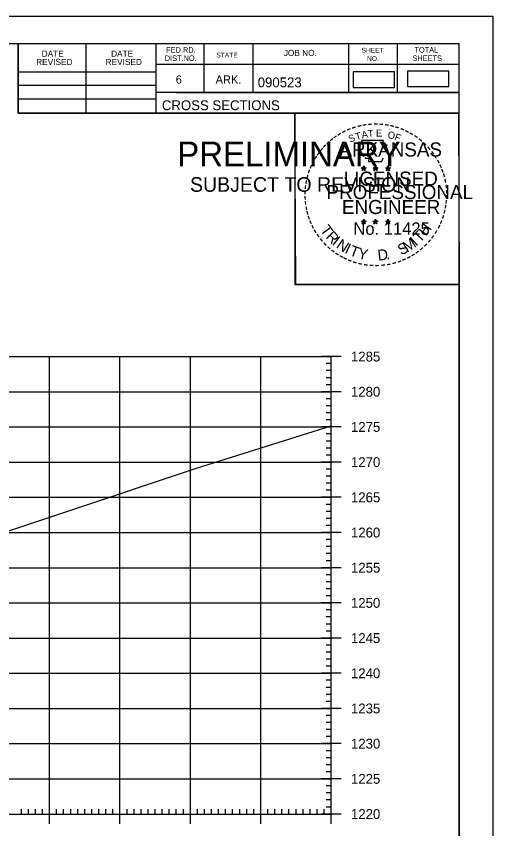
# Model space of a CAD drawing. Extents: x 1406028 to 1412453, y 321733 to 325986.
# Drawn here: x 1410874.9 to 1410942.5, y 322148 to 322263.4 of the extents above; entities that cross this region are included whole.
import ezdxf

# ---------------------------------------------------------------- set-up
doc = ezdxf.new("R2010")
doc.units = 0
for name, color, linetype in [('R_Axis', 7, 'Continuous'), ('R_Axis Annot', 7, 'Continuous'), ('R_Border', 7, 'Continuous'), ('R_Border PE', 7, 'Continuous'), ('R_Border Prem', 7, 'Continuous'), ('R_Exist Surface', 7, 'Continuous'), ('R_Fin Surface', 7, 'Continuous'), ('R_Grid', 7, 'Continuous'), ('R_No Plot', 7, 'Continuous')]:
    doc.layers.add(name, color=color, linetype=linetype)

msp = doc.modelspace()

# ---------------------------------------------------------------- linework, layer by layer
at = {"layer": 'R_Axis'}
for p, q in [((1410920.99, 322215.09), (1410918.19, 322215.09)), ((1410919.59, 322214.09), (1410918.89, 322214.09)), ((1410919.59, 322150.09), (1410919.59, 322215.09)), ((1410919.59, 322213.09), (1410918.89, 322213.09)), ((1410919.59, 322212.09), (1410918.89, 322212.09)), ((1410919.59, 322211.09), (1410918.89, 322211.09)), ((1410920.99, 322210.09), (1410918.19, 322210.09)), ((1410919.59, 322209.09), (1410918.89, 322209.09)), ((1410919.59, 322208.09), (1410918.89, 322208.09)), ((1410919.59, 322207.09), (1410918.89, 322207.09)), ((1410919.59, 322206.09), (1410918.89, 322206.09)), ((1410920.99, 322205.09), (1410918.19, 322205.09)), ((1410919.59, 322204.09), (1410918.89, 322204.09)), ((1410919.59, 322203.09), (1410918.89, 322203.09)), ((1410919.59, 322202.09), (1410918.89, 322202.09)), ((1410919.59, 322201.09), (1410918.89, 322201.09)), ((1410920.99, 322200.09), (1410918.19, 322200.09)), ((1410919.59, 322199.09), (1410918.89, 322199.09)), ((1410919.59, 322198.09), (1410918.89, 322198.09)), ((1410919.59, 322197.09), (1410918.89, 322197.09)), ((1410919.59, 322196.09), (1410918.89, 322196.09)), ((1410920.99, 322195.09), (1410918.19, 322195.09)), ((1410919.59, 322194.09), (1410918.89, 322194.09)), ((1410919.59, 322193.09), (1410918.89, 322193.09)), ((1410919.59, 322192.09), (1410918.89, 322192.09)), ((1410919.59, 322191.09), (1410918.89, 322191.09)), ((1410920.99, 322190.09), (1410918.19, 322190.09)), ((1410919.59, 322189.09), (1410918.89, 322189.09)), ((1410919.59, 322188.09), (1410918.89, 322188.09)), ((1410919.59, 322187.09), (1410918.89, 322187.09)), ((1410919.59, 322186.09), (1410918.89, 322186.09)), ((1410920.99, 322185.09), (1410918.19, 322185.09)), ((1410919.59, 322184.09), (1410918.89, 322184.09)), ((1410919.59, 322183.09), (1410918.89, 322183.09)), ((1410919.59, 322182.09), (1410918.89, 322182.09)), ((1410919.59, 322181.09), (1410918.89, 322181.09)), ((1410920.99, 322180.09), (1410918.19, 322180.09)), ((1410919.59, 322179.09), (1410918.89, 322179.09)), ((1410919.59, 322178.09), (1410918.89, 322178.09)), ((1410919.59, 322177.09), (1410918.89, 322177.09)), ((1410919.59, 322176.09), (1410918.89, 322176.09)), ((1410920.99, 322175.09), (1410918.19, 322175.09)), ((1410919.59, 322174.09), (1410918.89, 322174.09)), ((1410919.59, 322173.09), (1410918.89, 322173.09)), ((1410919.59, 322172.09), (1410918.89, 322172.09)), ((1410919.59, 322171.09), (1410918.89, 322171.09)), ((1410920.99, 322170.09), (1410918.19, 322170.09)), ((1410919.59, 322169.09), (1410918.89, 322169.09)), ((1410919.59, 322168.09), (1410918.89, 322168.09)), ((1410919.59, 322167.09), (1410918.89, 322167.09)), ((1410919.59, 322166.09), (1410918.89, 322166.09)), ((1410920.99, 322165.09), (1410918.19, 322165.09)), ((1410919.59, 322164.09), (1410918.89, 322164.09)), ((1410919.59, 322163.09), (1410918.89, 322163.09)), ((1410919.59, 322162.09), (1410918.89, 322162.09)), ((1410919.59, 322161.09), (1410918.89, 322161.09)), ((1410920.99, 322160.09), (1410918.19, 322160.09)), ((1410919.59, 322159.09), (1410918.89, 322159.09)), ((1410919.59, 322158.09), (1410918.89, 322158.09)), ((1410919.59, 322157.09), (1410918.89, 322157.09)), ((1410919.59, 322156.09), (1410918.89, 322156.09)), ((1410920.99, 322155.09), (1410918.19, 322155.09)), ((1410919.59, 322154.09), (1410918.89, 322154.09)), ((1410919.59, 322153.09), (1410918.89, 322153.09)), ((1410919.59, 322152.09), (1410918.89, 322152.09)), ((1410875.59, 322150.09), (1410875.59, 322150.79)), ((1410876.59, 322150.09), (1410876.59, 322150.79)), ((1410877.59, 322150.09), (1410877.59, 322150.79)), ((1410878.59, 322150.09), (1410878.59, 322150.79)), ((1410879.59, 322148.69), (1410879.59, 322151.49)), ((1410880.59, 322150.09), (1410880.59, 322150.79)), ((1410881.59, 322150.09), (1410881.59, 322150.79)), ((1410882.59, 322150.09), (1410882.59, 322150.79)), ((1410883.59, 322150.09), (1410883.59, 322150.79)), ((1410884.59, 322150.09), (1410884.59, 322150.79)), ((1410885.59, 322150.09), (1410885.59, 322150.79)), ((1410886.59, 322150.09), (1410886.59, 322150.79)), ((1410887.59, 322150.09), (1410887.59, 322150.79)), ((1410888.59, 322150.09), (1410888.59, 322150.79)), ((1410889.59, 322148.69), (1410889.59, 322151.49)), ((1410890.59, 322150.09), (1410890.59, 322150.79)), ((1410891.59, 322150.09), (1410891.59, 322150.79)), ((1410892.59, 322150.09), (1410892.59, 322150.79)), ((1410893.59, 322150.09), (1410893.59, 322150.79)), ((1410894.59, 322150.09), (1410894.59, 322150.79)), ((1410895.59, 322150.09), (1410895.59, 322150.79)), ((1410896.59, 322150.09), (1410896.59, 322150.79)), ((1410897.59, 322150.09), (1410897.59, 322150.79)), ((1410898.59, 322150.09), (1410898.59, 322150.79)), ((1410899.59, 322148.69), (1410899.59, 322151.49)), ((1410900.59, 322150.09), (1410900.59, 322150.79)), ((1410901.59, 322150.09), (1410901.59, 322150.79)), ((1410902.59, 322150.09), (1410902.59, 322150.79)), ((1410903.59, 322150.09), (1410903.59, 322150.79)), ((1410904.59, 322150.09), (1410904.59, 322150.79)), ((1410905.59, 322150.09), (1410905.59, 322150.79)), ((1410906.59, 322150.09), (1410906.59, 322150.79)), ((1410907.59, 322150.09), (1410907.59, 322150.79)), ((1410908.59, 322150.09), (1410908.59, 322150.79)), ((1410909.59, 322148.69), (1410909.59, 322151.49)), ((1410910.59, 322150.09), (1410910.59, 322150.79)), ((1410911.59, 322150.09), (1410911.59, 322150.79)), ((1410912.59, 322150.09), (1410912.59, 322150.79)), ((1410913.59, 322150.09), (1410913.59, 322150.79)), ((1410914.59, 322150.09), (1410914.59, 322150.79)), ((1410915.59, 322150.09), (1410915.59, 322150.79)), ((1410916.59, 322150.09), (1410916.59, 322150.79)), ((1410917.59, 322150.09), (1410917.59, 322150.79)), ((1410918.59, 322150.09), (1410918.59, 322150.79)), ((1410919.59, 322151.09), (1410918.89, 322151.09)), ((1410919.59, 322148.69), (1410919.59, 322151.49)), ((1410639.59, 322150.09), (1410919.59, 322150.09)), ((1410920.99, 322150.09), (1410918.19, 322150.09))]:
    msp.add_line(p, q, dxfattribs=at)
at = {"layer": 'R_Border'}
for p, q in [((1410621.59, 322259.55), (1410937.77, 322259.55)), ((1410875.13, 322249.67), (1410875.13, 322259.55)), ((1410884.81, 322249.67), (1410884.81, 322259.55)), ((1410894.67, 322259.55), (1410894.67, 322249.67)), ((1410901.51, 322259.55), (1410901.51, 322252.61)), ((1410908.45, 322259.55), (1410908.45, 322252.61)), ((1410922.03, 322259.55), (1410922.03, 322252.61)), ((1410928.97, 322259.55), (1410928.97, 322252.61)), ((1410937.77, 322054.09), (1410937.77, 322259.55)), ((1410937.77, 322256.61), (1410894.67, 322256.61)), ((1410937.77, 322256.63), (1410937.77, 322256.63)), ((1410875.13, 322255.53), (1410894.67, 322255.53)), ((1410875.13, 322253.67), (1410894.67, 322253.67)), ((1410937.77, 322252.61), (1410894.67, 322252.61)), ((1410897.63, 322252.61), (1410937.77, 322252.61)), ((1410875.13, 322251.73), (1410894.67, 322251.73)), ((1410937.77, 322249.67), (1410875.13, 322249.67))]:
    msp.add_line(p, q, dxfattribs=at)
at = {"layer": 'R_Border PE'}
for p, q in [((1410923.86, 322241.92), (1410924.21, 322241.81)), ((1410923.86, 322241.92), (1410924.11, 322241.88)), ((1410923.86, 322241.92), (1410924.09, 322241.8)), ((1410923.99, 322241.52), (1410924.21, 322241.81)), ((1410924.21, 322242.18), (1410924.16, 322241.93)), ((1410924.21, 322241.81), (1410924.21, 322242.18)), ((1410924.21, 322242.18), (1410924.25, 322241.93)), ((1410924.55, 322241.92), (1410924.21, 322241.81)), ((1410924.42, 322241.52), (1410924.21, 322241.81)), ((1410924.55, 322241.92), (1410924.27, 322241.88)), ((1410924.42, 322241.52), (1410924.28, 322241.81)), ((1410924.55, 322241.92), (1410924.35, 322241.82)), ((1410925.53, 322241.92), (1410925.88, 322241.81)), ((1410925.53, 322241.92), (1410925.78, 322241.88)), ((1410925.53, 322241.92), (1410925.76, 322241.8)), ((1410925.66, 322241.52), (1410925.88, 322241.81)), ((1410925.88, 322242.18), (1410925.83, 322241.93)), ((1410925.88, 322241.81), (1410925.88, 322242.18)), ((1410925.88, 322242.18), (1410925.92, 322241.93)), ((1410926.22, 322241.92), (1410925.88, 322241.81)), ((1410926.09, 322241.52), (1410925.88, 322241.81)), ((1410926.22, 322241.92), (1410925.94, 322241.88)), ((1410926.09, 322241.52), (1410925.95, 322241.81)), ((1410926.22, 322241.92), (1410926.02, 322241.82)), ((1410927.29, 322241.91), (1410927.64, 322241.8)), ((1410927.29, 322241.91), (1410927.54, 322241.87)), ((1410927.29, 322241.91), (1410927.53, 322241.79)), ((1410927.42, 322241.5), (1410927.64, 322241.8)), ((1410927.64, 322242.17), (1410927.6, 322241.91)), ((1410927.64, 322241.8), (1410927.64, 322242.17)), ((1410927.64, 322242.17), (1410927.69, 322241.92)), ((1410927.99, 322241.91), (1410927.64, 322241.8)), ((1410927.85, 322241.5), (1410927.64, 322241.8)), ((1410927.99, 322241.91), (1410927.7, 322241.86)), ((1410927.85, 322241.5), (1410927.72, 322241.8)), ((1410927.99, 322241.91), (1410927.78, 322241.81)), ((1410923.99, 322241.52), (1410924.12, 322241.76)), ((1410923.99, 322241.52), (1410924.2, 322241.73)), ((1410924.42, 322241.52), (1410924.2, 322241.73)), ((1410925.66, 322241.52), (1410925.79, 322241.76)), ((1410925.66, 322241.52), (1410925.87, 322241.73)), ((1410926.09, 322241.52), (1410925.87, 322241.73)), ((1410927.42, 322241.5), (1410927.55, 322241.75)), ((1410927.42, 322241.5), (1410927.64, 322241.72)), ((1410927.85, 322241.5), (1410927.64, 322241.72)), ((1410923.85, 322234.35), (1410924.2, 322234.24)), ((1410923.85, 322234.35), (1410924.11, 322234.31)), ((1410923.85, 322234.35), (1410924.09, 322234.23)), ((1410923.99, 322233.94), (1410924.2, 322234.24)), ((1410923.99, 322233.94), (1410924.11, 322234.19)), ((1410923.99, 322233.94), (1410924.2, 322234.16)), ((1410924.2, 322234.61), (1410924.16, 322234.35)), ((1410924.2, 322234.24), (1410924.2, 322234.61)), ((1410924.2, 322234.61), (1410924.25, 322234.36)), ((1410924.55, 322234.35), (1410924.2, 322234.24)), ((1410924.41, 322233.94), (1410924.2, 322234.24)), ((1410924.41, 322233.94), (1410924.2, 322234.16)), ((1410924.55, 322234.35), (1410924.26, 322234.3)), ((1410924.41, 322233.94), (1410924.28, 322234.23)), ((1410924.55, 322234.35), (1410924.34, 322234.25)), ((1410925.52, 322234.35), (1410925.87, 322234.24)), ((1410925.52, 322234.35), (1410925.77, 322234.31)), ((1410925.52, 322234.35), (1410925.76, 322234.23)), ((1410925.65, 322233.94), (1410925.87, 322234.24)), ((1410925.65, 322233.94), (1410925.78, 322234.19)), ((1410925.65, 322233.94), (1410925.87, 322234.16)), ((1410925.87, 322234.61), (1410925.83, 322234.35)), ((1410925.87, 322234.24), (1410925.87, 322234.61)), ((1410925.87, 322234.61), (1410925.92, 322234.36)), ((1410926.22, 322234.35), (1410925.87, 322234.24)), ((1410926.08, 322233.94), (1410925.87, 322234.24)), ((1410926.08, 322233.94), (1410925.87, 322234.16)), ((1410926.22, 322234.35), (1410925.93, 322234.3)), ((1410926.08, 322233.94), (1410925.95, 322234.23)), ((1410926.22, 322234.35), (1410926.01, 322234.25)), ((1410927.29, 322234.34), (1410927.64, 322234.23)), ((1410927.29, 322234.34), (1410927.54, 322234.3)), ((1410927.29, 322234.34), (1410927.53, 322234.22)), ((1410927.42, 322233.93), (1410927.64, 322234.23)), ((1410927.42, 322233.93), (1410927.55, 322234.18)), ((1410927.42, 322233.93), (1410927.64, 322234.15)), ((1410927.64, 322234.6), (1410927.6, 322234.34)), ((1410927.64, 322234.23), (1410927.64, 322234.6)), ((1410927.64, 322234.6), (1410927.69, 322234.35)), ((1410927.98, 322234.34), (1410927.64, 322234.23)), ((1410927.85, 322233.93), (1410927.64, 322234.23)), ((1410927.85, 322233.93), (1410927.64, 322234.15)), ((1410927.98, 322234.34), (1410927.7, 322234.29)), ((1410927.85, 322233.93), (1410927.71, 322234.22)), ((1410927.98, 322234.34), (1410927.78, 322234.24))]:
    msp.add_line(p, q, dxfattribs=at)
for points in [[(1410923.9, 322245.8), (1410924.17, 322244.98)], [(1410927.41, 322244.88), (1410927.55, 322245.16), (1410926.87, 322245.14), (1410927.01, 322245.8), (1410923.9, 322245.8)], [(1410924.39, 322243.38), (1410924.39, 322243.29), (1410924.95, 322243.27), (1410924.9, 322242.8), (1410926.77, 322242.8), (1410926.97, 322243.34)], [(1410924.21, 322242.18), (1410924.42, 322241.52), (1410923.86, 322241.92), (1410924.55, 322241.92), (1410923.99, 322241.52), (1410924.21, 322242.18)], [(1410925.88, 322242.18), (1410926.09, 322241.52), (1410925.53, 322241.92), (1410926.22, 322241.92), (1410925.66, 322241.52), (1410925.88, 322242.18)], [(1410927.64, 322242.17), (1410927.85, 322241.5), (1410927.29, 322241.91), (1410927.99, 322241.91), (1410927.42, 322241.5), (1410927.64, 322242.17)], [(1410924.2, 322234.61), (1410924.41, 322233.94), (1410923.85, 322234.35), (1410924.55, 322234.35), (1410923.99, 322233.94), (1410924.2, 322234.61)], [(1410925.87, 322234.61), (1410926.08, 322233.94), (1410925.52, 322234.35), (1410926.22, 322234.35), (1410925.65, 322233.94), (1410925.87, 322234.61)], [(1410927.64, 322234.6), (1410927.85, 322233.93), (1410927.29, 322234.34), (1410927.98, 322234.34), (1410927.42, 322233.93), (1410927.64, 322234.6)]]:
    msp.add_lwpolyline(points, dxfattribs=at)
for centre, radius in [((1410924.2, 322241.81), 0.172), ((1410924.2, 322241.81), 0.145), ((1410924.2, 322241.81), 0.116), ((1410924.2, 322241.81), 0.0991), ((1410924.2, 322241.81), 0.0747), ((1410924.2, 322241.81), 0.0495), ((1410924.2, 322241.81), 0.0296), ((1410925.87, 322241.81), 0.172), ((1410925.87, 322241.81), 0.145), ((1410925.87, 322241.81), 0.116), ((1410925.87, 322241.81), 0.0991), ((1410925.87, 322241.81), 0.0747), ((1410925.87, 322241.81), 0.0495), ((1410925.87, 322241.81), 0.0296), ((1410927.64, 322241.8), 0.172), ((1410927.64, 322241.8), 0.145), ((1410927.64, 322241.8), 0.116), ((1410927.64, 322241.8), 0.0991), ((1410927.64, 322241.8), 0.0747), ((1410927.64, 322241.8), 0.0495), ((1410927.64, 322241.8), 0.0296), ((1410924.2, 322234.24), 0.172), ((1410924.2, 322234.24), 0.145), ((1410924.2, 322234.24), 0.116), ((1410924.2, 322234.24), 0.0991), ((1410924.2, 322234.24), 0.0747), ((1410924.2, 322234.24), 0.0495), ((1410924.2, 322234.24), 0.0296), ((1410925.87, 322234.24), 0.172), ((1410925.87, 322234.24), 0.145), ((1410925.87, 322234.24), 0.116), ((1410925.87, 322234.24), 0.0991), ((1410925.87, 322234.24), 0.0747), ((1410925.87, 322234.24), 0.0495), ((1410925.87, 322234.24), 0.0296), ((1410927.64, 322234.23), 0.172), ((1410927.64, 322234.23), 0.145), ((1410927.64, 322234.23), 0.116), ((1410927.64, 322234.23), 0.0991), ((1410927.64, 322234.23), 0.0747), ((1410927.64, 322234.23), 0.0495), ((1410927.64, 322234.23), 0.0296)]:
    msp.add_circle(centre, radius, dxfattribs=at)
at = {"layer": 'R_Exist Surface'}
msp.add_lwpolyline([(1410817.84, 322168.51), (1410860.58, 322185.91), (1410864.16, 322187.1), (1410900.45, 322199.21), (1410919.59, 322205.24)], dxfattribs=at)
at = {"layer": 'R_Fin Surface'}
for points in [[(1410930.44, 322253.46), (1410936.28, 322253.46), (1410936.28, 322255.64), (1410930.44, 322255.64)], [(1410922.72, 322253.34), (1410928.56, 322253.34), (1410928.56, 322255.53), (1410922.72, 322255.53)]]:
    msp.add_lwpolyline(points, close=True, dxfattribs=at)
at = {"layer": 'R_Grid'}
for p, q in [((1410639.59, 322215.09), (1410919.59, 322215.09)), ((1410879.59, 322150.09), (1410879.59, 322215.09)), ((1410889.59, 322150.09), (1410889.59, 322215.09)), ((1410899.59, 322150.09), (1410899.59, 322215.09)), ((1410909.59, 322150.09), (1410909.59, 322215.09)), ((1410919.59, 322150.09), (1410919.59, 322215.09)), ((1410639.59, 322210.09), (1410919.59, 322210.09)), ((1410639.59, 322205.09), (1410919.59, 322205.09)), ((1410639.59, 322200.09), (1410919.59, 322200.09)), ((1410639.59, 322195.09), (1410919.59, 322195.09)), ((1410639.59, 322190.09), (1410919.59, 322190.09)), ((1410639.59, 322185.09), (1410919.59, 322185.09)), ((1410639.59, 322180.09), (1410919.59, 322180.09)), ((1410639.59, 322175.09), (1410919.59, 322175.09)), ((1410639.59, 322170.09), (1410919.59, 322170.09)), ((1410639.59, 322165.09), (1410919.59, 322165.09)), ((1410639.59, 322160.09), (1410919.59, 322160.09)), ((1410639.59, 322155.09), (1410919.59, 322155.09)), ((1410639.59, 322150.09), (1410919.59, 322150.09))]:
    msp.add_line(p, q, dxfattribs=at)
at = {"layer": 'R_No Plot'}
for p, q in [((1410609.19, 322263.44), (1410942.52, 322263.44)), ((1410913.81, 322227.21), (1410913.81, 322227.21))]:
    msp.add_line(p, q, dxfattribs=at)
for points in [[(1410609.18, 322263.44), (1410942.52, 322263.44), (1410942.52, 322050.11), (1410609.18, 322050.11)], [(1410855.51, 322259.55), (1410875.13, 322259.55), (1410875.13, 322249.67), (1410891.24, 322249.67), (1410914.44, 322249.67), (1410914.44, 322225.34), (1410937.77, 322225.34), (1410937.77, 322054.09), (1410621.59, 322054.09), (1410621.59, 322259.55)], [(1410914.44, 322249.67), (1410937.65, 322249.67), (1410937.77, 322225.34), (1410914.56, 322225.34)]]:
    msp.add_lwpolyline(points, close=True, dxfattribs=at)

# ---------------------------------------------------------------- texts
at = {"layer": 'R_Axis Annot'}
for s, p in [('1285', (1410922.39, 322214.39)), ('1280', (1410922.39, 322209.39)), ('1275', (1410922.39, 322204.39)), ('1270', (1410922.39, 322199.39)), ('1265', (1410922.39, 322194.39)), ('1260', (1410922.39, 322189.39)), ('1255', (1410922.39, 322184.39)), ('1250', (1410922.39, 322179.39)), ('1245', (1410922.39, 322174.39)), ('1240', (1410922.39, 322169.39)), ('1235', (1410922.39, 322164.39)), ('1230', (1410922.39, 322159.39)), ('1225', (1410922.39, 322154.39)), ('1220', (1410922.39, 322149.39))]:
    msp.add_text(s, height=1.4, dxfattribs=at).set_placement(p)
at = {"layer": 'R_Border'}
for s, height, p in [('DATE', 0.879, (1410878.47, 322257.69)), ('DATE', 0.879, (1410888.33, 322257.69)), ('FED.RD.', 0.782, (1410896.15, 322258.27)), ('STATE', 0.684, (1410903.27, 322257.59)), ('JOB NO.', 0.879, (1410912.85, 322257.79)), ('SHEET', 0.684, (1410923.89, 322258.27)), ('TOTAL', 0.782, (1410931.41, 322258.27)), ('REVISED', 0.879, (1410877.69, 322256.51)), ('REVISED', 0.879, (1410887.55, 322256.51)), ('DIST.NO.', 0.782, (1410895.95, 322257.09)), ('NO.', 0.684, (1410924.67, 322257.09)), ('SHEETS', 0.782, (1410931.13, 322257.09)), ('6', 1.17, (1410897.51, 322253.87)), ('ARK.', 1.172, (1410903.17, 322253.87)), ('090523', 1.4, (1410909.15, 322253.35)), ('CROSS SECTIONS', 1.4, (1410895.54, 322250.1))]:
    msp.add_text(s, height=height, rotation=360, dxfattribs=at).set_placement(p)
at = {"layer": 'R_Border PE'}
for s, height, rotation, p in [('-', 1.6, 24.3072, (1410922.01, 322246.66)), ('-', 1.6, 19.1761, (1410922.65, 322246.93)), ('-', 1.6, 13.6301, (1410923.4, 322247.17)), ('-', 1.6, 10.2193, (1410924.07, 322247.33)), ('-', 1.6, 5.8968, (1410924.8, 322247.44)), ('-', 1.6, 0.1862, (1410925.57, 322247.51)), ('-', 1.6, 357.743, (1410926.3, 322247.5)), ('-', 1.6, 352.1617, (1410927.04, 322247.45)), ('-', 1.6, 347.2049, (1410927.76, 322247.33)), ('-', 1.6, 342.3362, (1410928.4, 322247.18)), ('-', 1.6, 337.8551, (1410929.13, 322246.95)), ('-', 1.6, 36.2317, (1410920.2, 322245.58)), ('-', 1.6, 34.0636, (1410920.78, 322245.97)), ('-', 1.6, 28.7918, (1410921.38, 322246.34)), ('S', 1, 21.594, (1410922.25, 322245.48)), ('T', 1, 16.4036, (1410923.17, 322245.81)), ('A', 1, 11.2132, (1410923.99, 322246.06)), ('T', 1, 6.0228, (1410924.84, 322246.23)), ('E', 1, 0.8323, (1410925.95, 322246.34)), ('O', 1, 350.4515, (1410927.55, 322246.13)), ('F', 1, 340.0707, (1410928.5, 322245.9)), ('-', 1.6, 334.1211, (1410929.76, 322246.68)), ('-', 1.6, 329.6409, (1410930.34, 322246.4)), ('-', 1.6, 325.8627, (1410930.98, 322246.04)), ('-', 1.6, 42.9622, (1410919.29, 322244.78)), ('-', 1.6, 38.9507, (1410919.73, 322245.2)), ('ARKANSAS', 2, 360, (1410920.75, 322243.51)), ('-', 1.6, 320.5297, (1410931.59, 322245.61)), ('-', 1.6, 315.5786, (1410932.19, 322245.12)), ('-', 1.6, 54.2325, (1410918.03, 322243.25)), ('-', 1.6, 50.6142, (1410918.44, 322243.82)), ('-', 1.6, 48.423, (1410918.85, 322244.31)), ('-', 1.6, 309.8797, (1410932.76, 322244.57)), ('-', 1.6, 306.6522, (1410933.29, 322243.97)), ('-', 1.6, 62.8713, (1410917.39, 322242.11)), ('-', 1.6, 58.0706, (1410917.71, 322242.73)), ('-', 1.4, 303.6753, (1410933.77, 322243.4)), ('-', 1.6, 299.6684, (1410934.09, 322242.8)), ('-', 1.6, 67.7743, (1410917.13, 322241.5)), ('DWB', 0.01, 360, (1410924.19, 322241.81)), ('DWB', 0.01, 360, (1410925.86, 322241.81)), ('DWB', 0.01, 360, (1410927.63, 322241.8)), ('-', 1.6, 294.6628, (1410934.42, 322242.19)), ('-', 1.6, 75.461, (1410916.72, 322240.16)), ('-', 1.6, 72.3945, (1410916.91, 322240.87)), ('LICENSED', 2, 360, (1410921.35, 322239.37)), ('-', 1.6, 290.5728, (1410934.67, 322241.61)), ('-', 1.6, 285.1233, (1410934.91, 322241.03)), ('-', 1.6, 81.2013, (1410916.59, 322239.44)), ('PROFESSIONAL', 2, 360, (1410918.92, 322237.46)), ('-', 1.6, 280.5493, (1410935.11, 322240.29)), ('-', 1.6, 276.5962, (1410935.27, 322239.52)), ('-', 1.6, 89.0622, (1410916.48, 322238.05)), ('-', 1.6, 85.1863, (1410916.51, 322238.75)), ('-', 1.6, 274.3301, (1410935.33, 322238.8)), ('-', 1.6, 94.1959, (1410916.52, 322237.33)), ('-', 1.6, 98.9479, (1410916.59, 322236.66)), ('ENGINEER', 2, 360, (1410921.11, 322235.34)), ('-', 1.6, 263.5172, (1410935.34, 322237.5)), ('-', 1.6, 269.9407, (1410935.36, 322238.16)), ('-', 1.6, 101.7149, (1410916.73, 322235.93)), ('-', 1.6, 260.9953, (1410935.27, 322236.84)), ('-', 1.6, 105.4578, (1410916.89, 322235.33)), ('-', 1.6, 109.0874, (1410917.1, 322234.7)), ('-', 1.6, 252.8681, (1410934.98, 322235.45)), ('-', 1.6, 255.7626, (1410935.16, 322236.17)), ('-', 1.6, 114.0643, (1410917.36, 322234.1)), ('-', 1.6, 115.7289, (1410917.66, 322233.49)), ('T', 1.54, 306.0406, (1410917.96, 322233.08)), ('No. 11425', 1.757, 360, (1410922.74, 322232.39)), ('DWB', 0.01, 360, (1410924.19, 322234.24)), ('DWB', 0.01, 360, (1410925.86, 322234.24)), ('DWB', 0.01, 360, (1410927.62, 322234.23)), ('H', 1.54, 54.6088, (1410933.08, 322232.11)), ('-', 1.6, 244.6197, (1410934.5, 322234.14)), ('-', 1.6, 247.8887, (1410934.76, 322234.77)), ('-', 1.6, 120.4471, (1410918.02, 322232.9)), ('R', 1.54, 314.005, (1410918.72, 322232.03)), ('T', 1.54, 46.6444, (1410932.19, 322231.17)), ('-', 1.6, 239.0712, (1410934.1, 322233.39)), ('-', 1.6, 125.8934, (1410918.42, 322232.34)), ('-', 1.6, 130.7181, (1410918.88, 322231.79)), ('I', 1.54, 321.9694, (1410919.62, 322231.1)), ('N', 1.54, 326.5002, (1410920.19, 322230.63)), ('M', 1.54, 32.6563, (1410930.35, 322229.85)), ('I', 1.54, 42.1136, (1410931.63, 322230.69)), ('-', 1.6, 231.2538, (1410933.27, 322232.17)), ('-', 1.6, 233.8452, (1410933.7, 322232.74)), ('-', 1.6, 134.2238, (1410919.4, 322231.24)), ('-', 1.6, 138.9338, (1410919.93, 322230.78)), ('-', 1.6, 144.6463, (1410920.48, 322230.37)), ('I', 1.54, 335.3603, (1410921.4, 322229.84)), ('T', 1.54, 339.8912, (1410922.06, 322229.51)), ('Y', 1.54, 347.8556, (1410923.28, 322229.07)), ('D', 1.54, 6.3969, (1410926.26, 322228.71)), ('S', 1.54, 26.9312, (1410929.51, 322229.44)), ('-', 1.6, 221.0851, (1410932.27, 322231.1)), ('-', 1.6, 225.7653, (1410932.79, 322231.61)), ('-', 1.6, 148.0898, (1410921.04, 322230)), ('-', 1.6, 151.5704, (1410921.62, 322229.68)), ('-', 1.6, 154.6002, (1410922.14, 322229.43)), ('.', 1.54, 13.7642, (1410927.45, 322228.84)), ('-', 1.6, 207.3568, (1410930.63, 322229.9)), ('-', 1.6, 212.2491, (1410931.19, 322230.24)), ('-', 1.6, 215.7363, (1410931.72, 322230.63)), ('-', 1.6, 158.5612, (1410922.77, 322229.18)), ('-', 1.6, 162.7983, (1410923.46, 322228.96)), ('-', 1.6, 167.5555, (1410924.17, 322228.8)), ('-', 1.6, 173.1155, (1410924.94, 322228.69)), ('-', 1.6, 176.5183, (1410925.69, 322228.64)), ('-', 1.6, 181.5918, (1410926.43, 322228.65)), ('-', 1.6, 185.8167, (1410927.24, 322228.73)), ('-', 1.6, 191.2858, (1410927.98, 322228.86)), ('-', 1.6, 195.4743, (1410928.71, 322229.06)), ('-', 1.6, 200.7184, (1410929.39, 322229.3)), ('-', 1.6, 204.2516, (1410930, 322229.58))]:
    msp.add_text(s, height=height, rotation=rotation, dxfattribs=at).set_placement(p)
at = {"layer": 'R_Border Prem'}
for s, height, p in [('PRELIMINARY', 3.5, (1410897.72, 322242.13)), ('DWB', 0.01, (1410898.47, 322243.98)), ('SUBJECT TO REVISION', 2.0751, (1410899.53, 322238.5))]:
    msp.add_text(s, height=height, rotation=360, dxfattribs=at).set_placement(p)

doc.saveas('drawing.dxf')
